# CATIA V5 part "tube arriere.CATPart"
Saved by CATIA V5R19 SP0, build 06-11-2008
Part number: tube arriere
Bounding box of the stored display mesh (mm): x 441 to 525.991, y -23 to 23, z 83.014 to 482.994
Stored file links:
  D:\thinkmotion-MPB\Dropbox\Pack 1 sylvain\CFAO_2010_yyang\yyang\CFAO_2010_yyang\tube arriere.CATPart
  D:\thinkmotion-MPB\Dropbox\Pack 1 sylvain\CFAO_2010_yyang\yyang\CFAO_2010_yyang\yyang.CATProduct
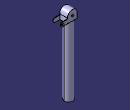
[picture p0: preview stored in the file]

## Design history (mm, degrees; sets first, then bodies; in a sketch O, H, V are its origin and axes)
External parameters (linked from other documents)
  `External.rayon interieur` = 18 mm
  `External.rayon1 du tube2` = 21 mm
  `External.longeur du tube` = 350 mm
  `External.hauteur du pivot plus haut` = 375 mm
  `External.hauteur du pivot plus bas` = 360 mm
  `External.rayon du trou des liaisons` = 5 mm
  `External.epaisseur de l'oreille` = 3 mm
  `External.demi_distance entre les oreilles` = 15 mm
  `External.epaisseur du pivot` = 2 mm
  `External.epaisseur du joint` = 3 mm
Set1
  Plane1: linked copy from another document
  Point1: linked copy from another document
  Plane2: linked copy from another document
  Point2: linked copy from another document
Body1 (main body)
  Sketch1 on Plane1, origin (0, 0, 83.0139), H (1, 0, 0), V (0, 1, 0)
    circle A1 centre (466, 0) radius 18
    point P1 (466, 0)
    reference projected point E1 (466, 0) from Point1
    reference projected point E2 (466, 0) from Point1
    circle A2 centre (466, 0) radius 21
    point P2 (466, 0)
    reference projected point E3 (466, 0) from Point1
    reference projected point E4 (466, 0) from Point1
    distance A1 E2 = 18 {= `External.rayon interieur`}
    distance A2 E4 = 21 {= `External.rayon1 du tube2`}
    coincidence: P1 E1, P2 E3
  Pad1: profile Sketch1, direction (0, 0, 1), length 350 {= `External.longeur du tube`}
  Sketch2 on Plane2, origin (0, 0, 0), H (-1, 0, 0), V (0, 0, 1)
    arc A1 centre (-466, 458.0139) radius 25 from (-441, 458.0139) to (-491, 458.0139) ccw
    point P1 (-466, 458.0139)
    reference projected point E1 (-466, 458.0139) from Point1
    reference projected point E2 (-466, 458.0139) from Point1
    line L1 (-516.01, 453.0139) -> (-491, 453.0139)
    line L2 (-441, 453.0139) -> (-441, 433.0139)
    line L3 (-441, 433.0139) -> (-516.01, 433.0139)
    arc A2 centre (-516.01, 443.0139) radius 10 from (-516.01, 453.0139) to (-516.01, 433.0139) ccw
    point P4 (-516.01, 443.0139)
    reference projected point E3 (-516.01, 443.0139) from Point2
    line L4 (-441, 453.0139) -> (-441, 458.0139)
    line L5 (-491, 458.0139) -> (-491, 453.0139)
    distance A1 E2 = 25 {= `External.hauteur du pivot plus haut`-`External.longeur du tube`}
    distance L1 L3 = 20 {= 2*(`External.hauteur du pivot plus bas`-`External.longeur du tube`)}
    coincidence: P1 E1, P4 E3
    horizontal: L1 H, L3 H
    vertical: L2 V, L5 V
    tangency: L2 A1, L3 A1, A2 L1, L4 A1, L5 A1
  Pad2: profile Sketch2, direction (0, 1, 0), length 20 {= `External.epaisseur de l'oreille`+`External.demi_distance entre les oreilles`+`External.epaisseur du pivot`}, mirrored extent
  Sketch3 on Plane2, origin (0, 0, 0), H (-1, 0, 0), V (0, 0, 1)
    line L1 (-526.01, 453.0139) -> (-491, 453.0139)
    line L2 (-491, 453.0139) -> (-491, 433.0139)
    line L3 (-491, 433.0139) -> (-526.01, 433.0139)
    line L4 (-526.01, 433.0139) -> (-526.01, 453.0139)
    reference projected line E1 (-491, 498.0139) -> (-491, 493.0139) from edge [face of Pad2 from Sketch2.L5 | end face of Pad2]
    reference projected line E2 (-491, 453.0139) -> (-516, 453.0139) from edge [face of Pad2 from Sketch2.L1 | end face of Pad2]
    reference projected line E3 (-516, 433.0139) -> (-441, 433.0139) from edge [face of Pad2 from Sketch2.L3 | end face of Pad2]
    reference projected arc E4 centre (-516.01, 443.0139) radius 10 from (-516.01, 453.0139) to (-516.01, 433.0139) ccw from edge [face of Pad2 from Sketch2.A2 | end face of Pad2]
    horizontal: L1 H, L3 H
    vertical: L2 V, L4 V
    coincidence: L2 E1, L1 E2, L3 E3
    tangency: E4 L4
  Pocket1: profile Sketch3, direction (0, -1, 0), length 18 {= `External.epaisseur de l'oreille`+`External.demi_distance entre les oreilles`}, mirrored extent
  Sketch4 on start face of Pad2, origin (0, -20, 0), H (1, 0, 0), V (0, 0, 1)
    circle A1 centre (466, 458.0139) radius 5
    point P1 (466, 458.0139)
    reference projected point E1 (466, 458.0139) from Point1
    reference projected point E2 (466, 458.0139) from Point1
    circle A2 centre (516.01, 443.0139) radius 5
    point P2 (516.01, 443.0139)
    reference projected point E3 (516.01, 443.0139) from Point2
    reference projected point E4 (516.01, 443.0139) from Point2
    distance A1 E2 = 5 {= `External.rayon du trou des liaisons`}
    distance A2 E4 = 5 {= `External.rayon du trou des liaisons`}
    coincidence: P1 E1, P2 E3
  Pad3: profile Sketch4, direction (0, -1, 0), length 3 {= `External.epaisseur du joint`}
  Mirror1: of Pad3, about Plane2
